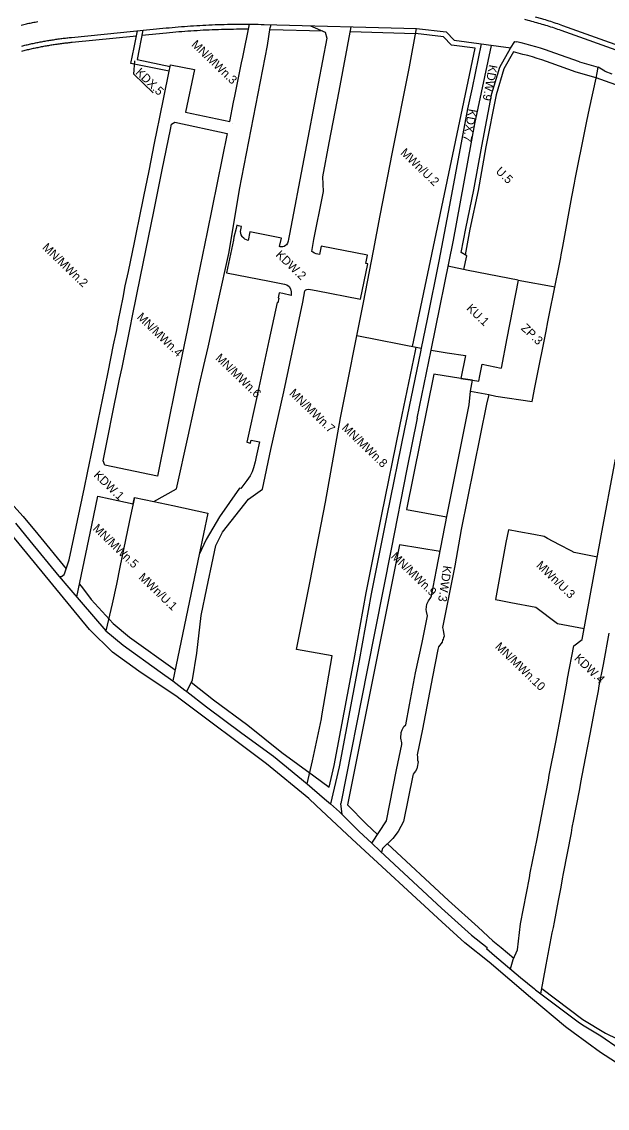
# Model space of a CAD drawing. Extents: x 7420063 to 7422255, y 5550978 to 5552824.
# Drawn here: x 7421322 to 7421664, y 5551045 to 5551680 of the extents above; entities that cross this region are included whole.
import ezdxf

# ---------------------------------------------------------------- set-up
doc = ezdxf.new("R2010")
doc.units = 0
for name, color, linetype in [('linie_rozgraniczajace', 7, 'Continuous'), ('linie_zabudowy_nieprzekraczalne', 7, 'Continuous'), ('oznaczenia_przeznaczen', 7, 'Continuous')]:
    doc.layers.add(name, color=color, linetype=linetype)

msp = doc.modelspace()

# ---------------------------------------------------------------- linework, layer by layer
at = {"layer": 'linie_rozgraniczajace'}
for p, q in [((7421467.12, 5551678.29), (7421466.86, 5551676.59)), ((7421574.29, 5551669.14), (7421607.39, 5551664.63)), ((7421609.77, 5551668.42), (7421610.69, 5551668.3)), ((7421647.52, 5551656.53), (7421633.14, 5551661.67)), ((7421647.52, 5551656.53), (7421658.55, 5551653.33)), ((7421662.4, 5551651.03), (7421658.55, 5551653.33)), ((7421662.4, 5551651.03), (7421666.5, 5551649.48)), ((7421444.89, 5551620.25), (7421444.89, 5551620.25)), ((7421611.73, 5551528.89), (7421633.34, 5551525.08)), ((7421517.45, 5551496.58), (7421555.07, 5551489.09)), ((7421552.77, 5551448.23), (7421560.95, 5551487.92)), ((7421583.86, 5551463.98), (7421584.97, 5551470.4)), ((7421612.02, 5551381.79), (7421605.99, 5551382.91)), ((7421620.83, 5551380.17), (7421612.02, 5551381.79)), ((7421626.85, 5551379.05), (7421620.83, 5551380.17)), ((7421628.91, 5551377.97), (7421626.85, 5551379.05)), ((7421635.79, 5551374.3), (7421628.91, 5551377.97)), ((7421642.6, 5551370.68), (7421635.79, 5551374.3)), ((7421598.48, 5551342.3), (7421601.49, 5551341.73)), ((7421601.49, 5551341.73), (7421607.38, 5551340.6)), ((7421607.38, 5551340.6), (7421622.06, 5551337.81)), ((7421622.06, 5551337.81), (7421634.61, 5551328.3)), ((7421634.61, 5551328.3), (7421650.32, 5551325.31)), ((7421508.94, 5551216.6), (7421508.18, 5551223.05))]:
    msp.add_line(p, q, dxfattribs=at)
for points in [[(7421615.34, 5551681.41), (7421617.36, 5551680.9), (7421618.4, 5551680.63), (7421619.43, 5551680.36), (7421620.46, 5551680.09), (7421621.49, 5551679.8), (7421622.52, 5551679.52), (7421623.54, 5551679.23), (7421624.57, 5551678.93), (7421625.59, 5551678.63), (7421626.61, 5551678.32), (7421627.63, 5551678.01), (7421628.65, 5551677.7), (7421629.66, 5551677.38), (7421630.68, 5551677.05), (7421631.69, 5551676.72), (7421632.7, 5551676.38), (7421633.7, 5551676.04), (7421634.71, 5551675.7), (7421635.71, 5551675.35), (7421636.71, 5551674.99), (7421744.05, 5551636.64)], [(7421321.4, 5551678.06), (7421322.13, 5551678.24), (7421322.87, 5551678.41), (7421323.6, 5551678.57), (7421324.34, 5551678.74), (7421325.07, 5551678.9), (7421325.81, 5551679.06), (7421326.55, 5551679.21), (7421327.28, 5551679.37), (7421328.02, 5551679.52), (7421328.76, 5551679.67), (7421329.5, 5551679.81), (7421330.24, 5551679.95), (7421330.98, 5551680.1)], [(7421321.64, 5551665.78), (7421322.77, 5551666.05), (7421323.46, 5551666.22), (7421324.15, 5551666.39), (7421324.85, 5551666.55), (7421325.54, 5551666.71), (7421326.23, 5551666.86), (7421326.93, 5551667.02), (7421327.62, 5551667.17), (7421328.32, 5551667.32), (7421329.01, 5551667.47), (7421329.71, 5551667.61), (7421330.41, 5551667.76), (7421331.11, 5551667.9), (7421331.8, 5551668.04), (7421332.5, 5551668.17), (7421333.2, 5551668.3), (7421333.9, 5551668.43), (7421334.6, 5551668.56), (7421335.3, 5551668.69), (7421336, 5551668.81), (7421336.7, 5551668.93), (7421337.4, 5551669.05), (7421338.1, 5551669.17), (7421338.8, 5551669.28), (7421339.51, 5551669.39), (7421340.21, 5551669.5), (7421340.91, 5551669.6), (7421341.61, 5551669.71), (7421342.32, 5551669.81), (7421343.02, 5551669.91), (7421343.72, 5551670), (7421344.43, 5551670.1), (7421345.13, 5551670.19), (7421345.84, 5551670.28), (7421346.54, 5551670.36), (7421347.25, 5551670.45), (7421347.95, 5551670.53), (7421348.66, 5551670.61), (7421349.36, 5551670.68), (7421350.07, 5551670.76), (7421350.78, 5551670.83), (7421405.99, 5551676.33), (7421407.78, 5551676.5), (7421409.57, 5551676.67), (7421411.35, 5551676.83), (7421413.14, 5551676.98), (7421414.93, 5551677.13), (7421416.71, 5551677.27), (7421418.5, 5551677.4), (7421420.29, 5551677.53), (7421422.08, 5551677.64), (7421423.87, 5551677.75), (7421425.66, 5551677.86), (7421427.46, 5551677.95), (7421429.25, 5551678.04), (7421431.04, 5551678.13), (7421432.83, 5551678.2), (7421434.63, 5551678.27), (7421436.42, 5551678.33), (7421438.21, 5551678.38), (7421440.01, 5551678.43), (7421441.8, 5551678.47), (7421443.59, 5551678.5), (7421445.39, 5551678.53), (7421447.18, 5551678.55), (7421448.98, 5551678.56), (7421450.77, 5551678.56), (7421452.56, 5551678.56), (7421454.36, 5551678.55), (7421456.15, 5551678.54), (7421457.94, 5551678.51), (7421459.74, 5551678.48), (7421461.53, 5551678.44), (7421463.33, 5551678.4), (7421552.25, 5551675.98)], [(7421343.48, 5551355.75), (7421343.95, 5551355.65), (7421344.9, 5551355.79), (7421345.74, 5551356.22), (7421346.44, 5551356.89), (7421346.91, 5551357.82), (7421347.25, 5551359.09), (7421349.41, 5551365.52), (7421358.38, 5551407.71), (7421360.09, 5551416.31), (7421363.34, 5551432.24), (7421364.9, 5551439.93), (7421366.27, 5551446.69), (7421368.99, 5551459.96), (7421370.35, 5551466.51), (7421372.1, 5551475.09), (7421375.31, 5551491.04), (7421376.92, 5551498.97), (7421378.24, 5551505.56), (7421380.97, 5551518.88), (7421382.15, 5551525.58), (7421384.06, 5551534.08), (7421387.49, 5551550.89), (7421388.88, 5551557.78), (7421390.24, 5551564.47), (7421392.96, 5551577.76), (7421396.05, 5551592.89), (7421399.27, 5551608.93), (7421400.83, 5551616.64), (7421402.19, 5551623.29), (7421404.9, 5551636.64), (7421407.62, 5551650.07), (7421408.5, 5551654.7), (7421422.51, 5551652.05), (7421417.36, 5551627.19), (7421443.21, 5551621.67), (7421445.42, 5551633.03), (7421446.12, 5551636.41), (7421450.11, 5551655.92), (7421450.77, 5551659.3), (7421454.67, 5551678.55)], [(7421353.75, 5551343.79), (7421362.69, 5551385.65), (7421366.11, 5551402.67), (7421373.3, 5551401.04), (7421382.32, 5551399.19), (7421386.68, 5551398.27), (7421387.44, 5551401.87), (7421398.74, 5551399.49), (7421411.99, 5551406.95), (7421418.8, 5551437.65), (7421425.56, 5551468.05), (7421428.09, 5551478.95), (7421430.63, 5551489.84), (7421436.62, 5551517.21), (7421442.61, 5551544.59), (7421445.55, 5551561.91), (7421448.95, 5551581.92), (7421465.25, 5551666), (7421466.86, 5551676.59)], [(7421407.8, 5551651.02), (7421385.46, 5551655.57), (7421387.3, 5551664.86), (7421389.35, 5551674.67)], [(7421392.49, 5551674.99), (7421389.04, 5551657.9), (7421408.35, 5551653.9)], [(7421490.32, 5551677.66), (7421498.93, 5551673.91), (7421499.99, 5551670.44), (7421494.93, 5551643.84), (7421478.18, 5551555.81)], [(7421488.39, 5551234.55), (7421491.59, 5551248.01), (7421496.7, 5551272.61), (7421497.06, 5551274.35), (7421503.12, 5551309.33), (7421482.24, 5551313.02), (7421490.09, 5551353.06), (7421499.09, 5551399.08), (7421507.89, 5551448.52), (7421521.29, 5551515.87), (7421527.15, 5551546.09), (7421531.12, 5551566.65), (7421538.27, 5551603.74), (7421548.27, 5551653.59), (7421552.25, 5551675.98)], [(7421491.2, 5551545.77), (7421492.4, 5551552.6), (7421497.61, 5551578.81), (7421497.99, 5551580.8), (7421497.49, 5551589.25), (7421501.32, 5551609.29), (7421507.05, 5551639.44), (7421514.21, 5551677.01)], [(7421552.25, 5551675.98), (7421569.57, 5551674.04), (7421574.29, 5551669.14)], [(7421579.87, 5551535.21), (7421581.67, 5551543.16), (7421578.46, 5551545.05), (7421581.07, 5551559.18), (7421585.88, 5551581.82), (7421590.4, 5551607.32), (7421596.36, 5551637.94), (7421600.98, 5551653.46), (7421607.28, 5551664.45), (7421609.77, 5551668.42)], [(7421590.15, 5551666.98), (7421584.77, 5551641.38), (7421582.18, 5551629.02), (7421571.55, 5551572.73), (7421565.29, 5551540.04), (7421558.48, 5551506.09), (7421555.07, 5551489.12), (7421554.62, 5551486.94), (7421546.89, 5551449.51), (7421545.28, 5551442.07), (7421534.95, 5551391.38), (7421525.87, 5551345.67), (7421518.88, 5551306.58), (7421507.21, 5551244.53), (7421502.04, 5551222.78)], [(7421560.95, 5551487.92), (7421573.88, 5551552.36), (7421586.47, 5551620.26), (7421596.11, 5551666.17)], [(7421594.59, 5551462.09), (7421598.62, 5551461.09), (7421619.87, 5551457.92), (7421620.26, 5551459.88), (7421621.32, 5551465.27), (7421622.29, 5551470.17), (7421628.03, 5551499.11), (7421629.11, 5551504.51), (7421630.08, 5551509.41), (7421635.82, 5551538.35), (7421636.58, 5551542.2), (7421636.87, 5551543.75), (7421637.78, 5551548.67), (7421643.16, 5551577.67), (7421644.64, 5551585.62), (7421645.11, 5551588.01), (7421650.92, 5551616.92), (7421651.92, 5551621.83), (7421653.39, 5551629.17), (7421657.21, 5551647.05), (7421657.85, 5551650.03), (7421658.55, 5551653.33)], [(7421478.18, 5551555.81), (7421477.57, 5551552.84), (7421477.33, 5551551.64), (7421476.99, 5551550.61), (7421476.34, 5551549.64), (7421475.7, 5551549.11), (7421474.99, 5551548.7), (7421474.17, 5551548.47), (7421473.3, 5551548.4), (7421472.55, 5551548.5), (7421472.31, 5551548.56), (7421473.34, 5551553.5), (7421454.9, 5551557.13), (7421453.87, 5551552.19), (7421453.02, 5551552.43), (7421452.08, 5551552.86), (7421451.32, 5551553.41), (7421450.73, 5551554.01), (7421450.35, 5551554.52), (7421449.86, 5551555.52), (7421449.6, 5551556.44), (7421449.53, 5551557.46), (7421449.62, 5551558.34), (7421450.04, 5551560.34), (7421449.07, 5551560.57), (7421448.28, 5551560.73), (7421447.31, 5551560.98), (7421446.94, 5551559.21), (7421445.59, 5551553.97), (7421445.28, 5551552.25), (7421441.36, 5551533.3), (7421466.44, 5551528.33), (7421475.2, 5551526.58), (7421476.63, 5551526.13), (7421477.84, 5551525.22), (7421478.68, 5551523.94), (7421479.14, 5551522.04), (7421479.11, 5551520), (7421474.29, 5551521.08), (7421472.14, 5551521.54), (7421471.48, 5551518.56), (7421471.88, 5551518.48), (7421471.32, 5551515.76), (7421470.89, 5551515.84), (7421466.07, 5551493.54), (7421463.1, 5551479.82), (7421459.58, 5551463.55), (7421459.16, 5551461.59), (7421453.16, 5551434.14), (7421455.29, 5551433.66), (7421455.66, 5551435.46), (7421460.54, 5551434.36), (7421460.15, 5551432.62), (7421458.59, 5551425.66), (7421457.96, 5551422.75), (7421457.07, 5551419.32), (7421456.29, 5551416.98), (7421455.05, 5551414.51), (7421453.23, 5551411.73), (7421449.59, 5551407.16), (7421448.84, 5551407.32)], [(7421487.09, 5551522.78), (7421487.59, 5551523.2), (7421488.17, 5551523.42), (7421488.95, 5551523.64), (7421490.46, 5551523.56), (7421493.69, 5551522.9), (7421519.68, 5551517.83), (7421523.79, 5551538.4), (7421522.61, 5551538.65), (7421523.59, 5551543.53), (7421496.58, 5551548.89), (7421495.61, 5551543.99), (7421493.72, 5551544.36), (7421492.69, 5551544.72), (7421491.82, 5551545.24), (7421491.23, 5551545.74), (7421491.2, 5551545.77)], [(7421611.73, 5551528.89), (7421582.58, 5551534.67), (7421570.67, 5551537.03)], [(7421611.73, 5551528.89), (7421605.17, 5551494.96), (7421601.78, 5551477.43)], [(7421418.07, 5551288.42), (7421421.38, 5551295.33), (7421423.96, 5551310.97), (7421426.51, 5551332.89), (7421429.88, 5551348.82), (7421433.57, 5551366.48), (7421435.1, 5551373.8), (7421436.61, 5551376.89), (7421439, 5551381.6), (7421454.2, 5551400.94), (7421462.3, 5551406.74), (7421467.2, 5551429.88), (7421474.74, 5551463.65), (7421485.9, 5551516.09), (7421487.09, 5551522.78)], [(7421560.95, 5551487.92), (7421570.15, 5551486.48), (7421580.87, 5551484.92), (7421578.26, 5551471.47), (7421584.97, 5551470.4), (7421588.64, 5551469.81), (7421589.26, 5551473.06), (7421590.68, 5551479.91), (7421601.78, 5551477.43)], [(7421526.24, 5551199.82), (7421534.76, 5551212.88), (7421540.65, 5551242.64), (7421543.66, 5551257.51), (7421543.8, 5551258.5), (7421543.14, 5551261.24), (7421543.39, 5551264.5), (7421543.85, 5551266.14), (7421544.96, 5551267.96), (7421546.17, 5551269.01), (7421548.12, 5551280.71), (7421551.67, 5551299.42), (7421555.56, 5551317.17), (7421558.67, 5551332.8), (7421558.07, 5551335.21), (7421557.99, 5551336.36), (7421558.41, 5551339.46), (7421559.33, 5551341.56), (7421560.71, 5551343.47), (7421561.06, 5551344.46), (7421564.04, 5551359.62), (7421570.14, 5551391.82), (7421582.99, 5551456.06), (7421583.86, 5551463.98), (7421594.59, 5551462.09), (7421593.13, 5551456.47), (7421578.37, 5551383.12), (7421574.65, 5551361.92), (7421567.5, 5551325.86), (7421567.84, 5551324.39), (7421568.18, 5551322.93), (7421568.26, 5551322.08), (7421568.38, 5551320.75), (7421568.04, 5551319.94), (7421567.8, 5551319.18), (7421567.56, 5551318.42), (7421567.22, 5551317.32), (7421565.18, 5551314.63), (7421564.87, 5551313.03), (7421561.72, 5551297), (7421555.82, 5551266.39), (7421552.61, 5551251.39), (7421552.97, 5551250.21), (7421552.96, 5551248.43), (7421553.22, 5551247.4), (7421553.04, 5551246.35), (7421552.85, 5551245.31), (7421552.68, 5551244.26), (7421552.51, 5551243.21), (7421551.82, 5551241.98), (7421550.87, 5551240.94), (7421550.37, 5551240.22), (7421550.2, 5551239.36), (7421544.77, 5551212.54), (7421541.68, 5551206.59), (7421538.45, 5551202.52), (7421532.52, 5551196.63), (7421531.9, 5551194.49)], [(7421552.77, 5551448.23), (7421546.65, 5551418.49), (7421537.44, 5551371.69), (7421523.57, 5551300.91), (7421508.18, 5551223.05)], [(7421607.22, 5551126.41), (7421608.81, 5551131.76), (7421611.29, 5551137.46), (7421613.17, 5551152.64), (7421618.42, 5551179.64), (7421618.82, 5551182.48), (7421622.84, 5551202.47), (7421626.06, 5551219.65), (7421629.36, 5551236.6), (7421629.86, 5551239.56), (7421633.64, 5551258.82), (7421637.07, 5551276.43), (7421640.11, 5551293.41), (7421640.57, 5551296.02), (7421644.31, 5551315.09), (7421649.13, 5551318.87), (7421660.29, 5551379.47), (7421668.57, 5551424.32)], [(7421387.44, 5551401.87), (7421385.19, 5551391.24), (7421383.45, 5551382.73), (7421379.03, 5551361.16), (7421376.99, 5551351.17), (7421374.39, 5551339.65), (7421370.84, 5551323.88)], [(7421387.44, 5551401.87), (7421398.74, 5551399.49), (7421409.97, 5551397.12)], [(7421448.84, 5551407.32), (7421437.19, 5551390.6), (7421429.5, 5551377.43), (7421425.29, 5551368.53)], [(7421409.97, 5551397.12), (7421430.36, 5551392.81), (7421425.29, 5551368.53), (7421409.86, 5551294.71)], [(7421318, 5551386.81), (7421326.34, 5551376.65), (7421343.35, 5551355.9), (7421343.48, 5551355.75), (7421349.14, 5551349.15), (7421370.84, 5551323.88), (7421380.89, 5551315.59), (7421402.48, 5551300.03), (7421409.9, 5551294.68), (7421416.9, 5551289.32), (7421418.07, 5551288.42), (7421429.57, 5551279.58), (7421450.17, 5551264.06), (7421468.69, 5551250.63), (7421488.39, 5551234.55), (7421498.62, 5551225.83), (7421502.04, 5551222.78), (7421507.29, 5551218.07), (7421508.94, 5551216.6), (7421518.88, 5551206.67), (7421526.24, 5551199.82), (7421531.14, 5551195.26), (7421566.99, 5551161.92), (7421584.41, 5551146.1), (7421593.64, 5551138.85), (7421593.12, 5551138.24)], [(7421605.99, 5551382.91), (7421604.6, 5551375.66), (7421598.48, 5551342.3)], [(7421710.25, 5551044.89), (7421659.87, 5551077.54), (7421643.79, 5551089.2), (7421639.35, 5551092.43), (7421619, 5551109.54), (7421594.8, 5551130.3), (7421580.52, 5551141.54), (7421567.1, 5551153.93), (7421514.8, 5551202.27), (7421493.67, 5551221.92), (7421489.35, 5551225.94), (7421464.63, 5551246.13), (7421414.29, 5551283.96), (7421412.45, 5551285.34), (7421390.05, 5551300.46), (7421374.75, 5551311.5), (7421361.22, 5551324.68), (7421339.77, 5551350.86), (7421315.74, 5551380.18)], [(7421658.01, 5551367.1), (7421644.47, 5551369.68), (7421642.6, 5551370.68)], [(7421624.89, 5551111.85), (7421628.11, 5551128.78), (7421631.67, 5551147.49), (7421632.27, 5551150.61), (7421632.86, 5551153.73), (7421635.24, 5551166.26), (7421635.81, 5551169.25), (7421636.75, 5551174.14), (7421637.67, 5551179.03), (7421638.25, 5551182.02), (7421640.52, 5551193.95), (7421642.79, 5551205.92), (7421643.36, 5551208.91), (7421644.28, 5551213.77), (7421645.22, 5551218.65), (7421645.79, 5551221.69), (7421647.69, 5551231.66), (7421648.39, 5551235.37), (7421651.07, 5551249.45), (7421653.75, 5551263.53), (7421654.53, 5551267.61), (7421656.14, 5551276.06), (7421656.71, 5551279.05), (7421657.64, 5551283.95), (7421658.57, 5551288.84), (7421659.14, 5551291.84), (7421661.52, 5551304.37), (7421664.97, 5551322.5)], [(7421593.12, 5551138.24), (7421597.97, 5551134.17), (7421613.17, 5551121.41), (7421621.17, 5551114.7), (7421621.83, 5551114.15), (7421624.89, 5551111.85), (7421647.59, 5551094.76), (7421650.29, 5551093.04), (7421660.04, 5551087.3), (7421670.76, 5551079.87)]]:
    msp.add_lwpolyline(points, dxfattribs=at)
msp.add_lwpolyline([(7421400.9, 5551414.39), (7421370.22, 5551420.71), (7421369.17, 5551423.35), (7421372.74, 5551440.92), (7421374.15, 5551447.85), (7421378.83, 5551470.98), (7421380.24, 5551477.93), (7421384.97, 5551501.08), (7421386.39, 5551508.01), (7421391.13, 5551531.03), (7421398.73, 5551569.11), (7421402.3, 5551586.63), (7421403.68, 5551593.36), (7421408.5, 5551616.96), (7421409.15, 5551620.15), (7421411, 5551621.29), (7421441.67, 5551614.65), (7421435.82, 5551585.87), (7421429.98, 5551557.06), (7421424.51, 5551530.48), (7421418.42, 5551500.4), (7421412.32, 5551470.41), (7421406.19, 5551440.38)], close=True, dxfattribs=at)
msp.add_arc((7421562.74, 5551464.62), 209.25, 70.33933, 76.75042, dxfattribs=at)
at = {"layer": 'linie_zabudowy_nieprzekraczalne'}
for p, q in [((7421586.55, 5551664.44), (7421572.85, 5551666.31)), ((7421584.97, 5551470.4), (7421578.26, 5551471.47))]:
    msp.add_line(p, q, dxfattribs=at)
for points in [[(7421621.7, 5551682.88), (7421625.41, 5551681.81), (7421626.45, 5551681.51), (7421627.48, 5551681.2), (7421628.51, 5551680.88), (7421629.54, 5551680.56), (7421630.57, 5551680.23), (7421631.6, 5551679.9), (7421632.63, 5551679.57), (7421633.65, 5551679.23), (7421634.67, 5551678.88), (7421635.69, 5551678.53), (7421636.71, 5551678.18), (7421637.71, 5551677.82), (7421745.06, 5551639.47)], [(7421454.07, 5551675.55), (7421452.55, 5551675.56), (7421450.77, 5551675.56), (7421448.99, 5551675.56), (7421447.21, 5551675.55), (7421445.43, 5551675.53), (7421443.64, 5551675.5), (7421441.86, 5551675.47), (7421440.08, 5551675.43), (7421438.3, 5551675.39), (7421436.52, 5551675.33), (7421434.73, 5551675.27), (7421432.95, 5551675.2), (7421431.17, 5551675.13), (7421429.39, 5551675.05), (7421427.61, 5551674.96), (7421425.83, 5551674.86), (7421424.05, 5551674.76), (7421422.27, 5551674.65), (7421420.5, 5551674.53), (7421418.72, 5551674.41), (7421416.94, 5551674.28), (7421415.16, 5551674.14), (7421413.39, 5551673.99), (7421411.61, 5551673.84), (7421409.84, 5551673.68), (7421408.07, 5551673.52), (7421406.28, 5551673.34), (7421391.87, 5551671.91)], [(7421497.66, 5551674.46), (7421466.66, 5551675.31)], [(7421388.71, 5551671.59), (7421351.08, 5551667.85), (7421350.38, 5551667.77), (7421349.68, 5551667.7), (7421348.99, 5551667.63), (7421348.29, 5551667.55), (7421347.6, 5551667.47), (7421346.9, 5551667.39), (7421346.21, 5551667.3), (7421345.51, 5551667.21), (7421344.82, 5551667.12), (7421344.13, 5551667.03), (7421343.43, 5551666.94), (7421342.74, 5551666.84), (7421342.05, 5551666.74), (7421341.35, 5551666.64), (7421340.66, 5551666.53), (7421339.97, 5551666.43), (7421339.28, 5551666.32), (7421338.59, 5551666.2), (7421337.89, 5551666.09), (7421337.2, 5551665.97), (7421336.51, 5551665.86), (7421335.82, 5551665.73), (7421335.13, 5551665.61), (7421334.44, 5551665.48), (7421333.76, 5551665.36), (7421333.07, 5551665.22), (7421332.38, 5551665.09), (7421331.69, 5551664.96), (7421331, 5551664.82), (7421330.32, 5551664.68), (7421329.63, 5551664.53), (7421328.95, 5551664.39), (7421328.26, 5551664.24), (7421327.58, 5551664.09), (7421326.89, 5551663.94), (7421326.21, 5551663.78), (7421325.53, 5551663.62), (7421324.84, 5551663.47), (7421324.16, 5551663.3), (7421323.48, 5551663.14), (7421322.8, 5551662.97), (7421322.12, 5551662.8), (7421321.44, 5551662.63)], [(7421551.72, 5551672.99), (7421513.64, 5551674.03)], [(7421572.85, 5551666.31), (7421568.16, 5551671.18), (7421551.73, 5551673.02)], [(7421549.95, 5551490.11), (7421586.55, 5551664.44)], [(7421608.93, 5551662.31), (7421603.3, 5551652.47), (7421598.79, 5551637.34), (7421592.86, 5551606.87), (7421588.33, 5551581.34), (7421583.52, 5551558.69), (7421580.75, 5551543.7)], [(7421657.25, 5551647.22), (7421645.6, 5551650.6), (7421631.04, 5551655.8)], [(7421708.1, 5551629.05), (7421657.25, 5551647.22)], [(7421501.27, 5551232.51), (7421504.27, 5551245.15), (7421515.93, 5551307.12), (7421522.92, 5551346.23), (7421532.01, 5551391.97), (7421542.34, 5551442.69), (7421543.95, 5551450.13), (7421551.68, 5551487.55), (7421552.12, 5551489.68)], [(7421562.34, 5551474.02), (7421546.55, 5551394.92), (7421569.89, 5551390.53)], [(7421578.26, 5551471.47), (7421562.34, 5551474.02)], [(7421304.35, 5551410.69), (7421322.54, 5551390.73), (7421330.98, 5551380.46), (7421347.61, 5551360.17)], [(7421566.05, 5551370.24), (7421542.4, 5551374.18), (7421512.07, 5551222.29)], [(7421355.33, 5551351.17), (7421357.09, 5551349.13), (7421362.26, 5551342.27), (7421375.06, 5551328.18), (7421384.56, 5551320.34), (7421411.2, 5551301.14)], [(7421420.72, 5551293.95), (7421433.68, 5551283.71), (7421453.73, 5551268.88), (7421473.6, 5551252.86), (7421492.23, 5551239.15), (7421501.27, 5551232.51)], [(7421512.07, 5551222.29), (7421523.04, 5551210.99), (7421529.56, 5551204.92)], [(7421535.4, 5551199.49), (7421571.05, 5551166.33), (7421588.29, 5551150.69), (7421596.98, 5551142.83), (7421601.83, 5551138.77), (7421609.18, 5551132.6)], [(7421625.48, 5551114.93), (7421649.55, 5551096.81), (7421662.74, 5551088.81), (7421682.85, 5551079.1)]]:
    msp.add_lwpolyline(points, dxfattribs=at)
msp.add_arc((7421562.74, 5551464.62), 203.02, 70.33933, 76.84746, dxfattribs=at)
at = {"layer": 'oznaczenia_przeznaczen'}
msp.add_lwpolyline([(7421398.52, 5551638.43), (7421387.19, 5551649.28), (7421387.64, 5551657.11)], dxfattribs=at)

# ---------------------------------------------------------------- texts
for s, rotation, p in [('MN/MWn.3', 316.21328, (7421420.42, 5551666.21)), ('KDX.5', 316.21328, (7421387.76, 5551649.85)), ('KDW.9', 259.61954, (7421594.75, 5551655.15)), ('KDX.7', 259.61954, (7421582.76, 5551629.33)), ('MWn/U.2', 316.21328, (7421542.57, 5551602.9)), ('U.5', 316.21328, (7421598.24, 5551592.07)), ('MN/MWn.2', 316.21328, (7421333.31, 5551547.55)), ('KDW.2', 316.21328, (7421469.67, 5551543.28)), ('MN/MWn.4', 316.21328, (7421388.57, 5551506.84)), ('KU.1', 316.21328, (7421581.13, 5551512.01)), ('ZP.3', 316.21328, (7421613.07, 5551500.41)), ('MN/MWn.6', 316.21328, (7421434.47, 5551482.88)), ('MN/MWn.7', 316.21328, (7421477.64, 5551462.33)), ('MN/MWn.8', 316.21328, (7421508.32, 5551442.11)), ('KDW.1', 316.21328, (7421363.32, 5551414.49)), ('MN/MWn.5', 316.21328, (7421362.83, 5551383.29)), ('MN/MWn.9', 316.21328, (7421537.02, 5551366.95)), ('MWn/U.3', 316.21328, (7421621.93, 5551361.74)), ('MWn/U.1', 316.21328, (7421389.55, 5551354.72)), ('KDW.3', 261.70043, (7421567.99, 5551362.32)), ('MN/MWn.10', 316.21328, (7421597.88, 5551314.23)), ('KDW.4', 316.21328, (7421644.16, 5551307.41))]:
    msp.add_text(s, height=5, rotation=rotation, dxfattribs=at).set_placement(p)

doc.saveas('drawing.dxf')
